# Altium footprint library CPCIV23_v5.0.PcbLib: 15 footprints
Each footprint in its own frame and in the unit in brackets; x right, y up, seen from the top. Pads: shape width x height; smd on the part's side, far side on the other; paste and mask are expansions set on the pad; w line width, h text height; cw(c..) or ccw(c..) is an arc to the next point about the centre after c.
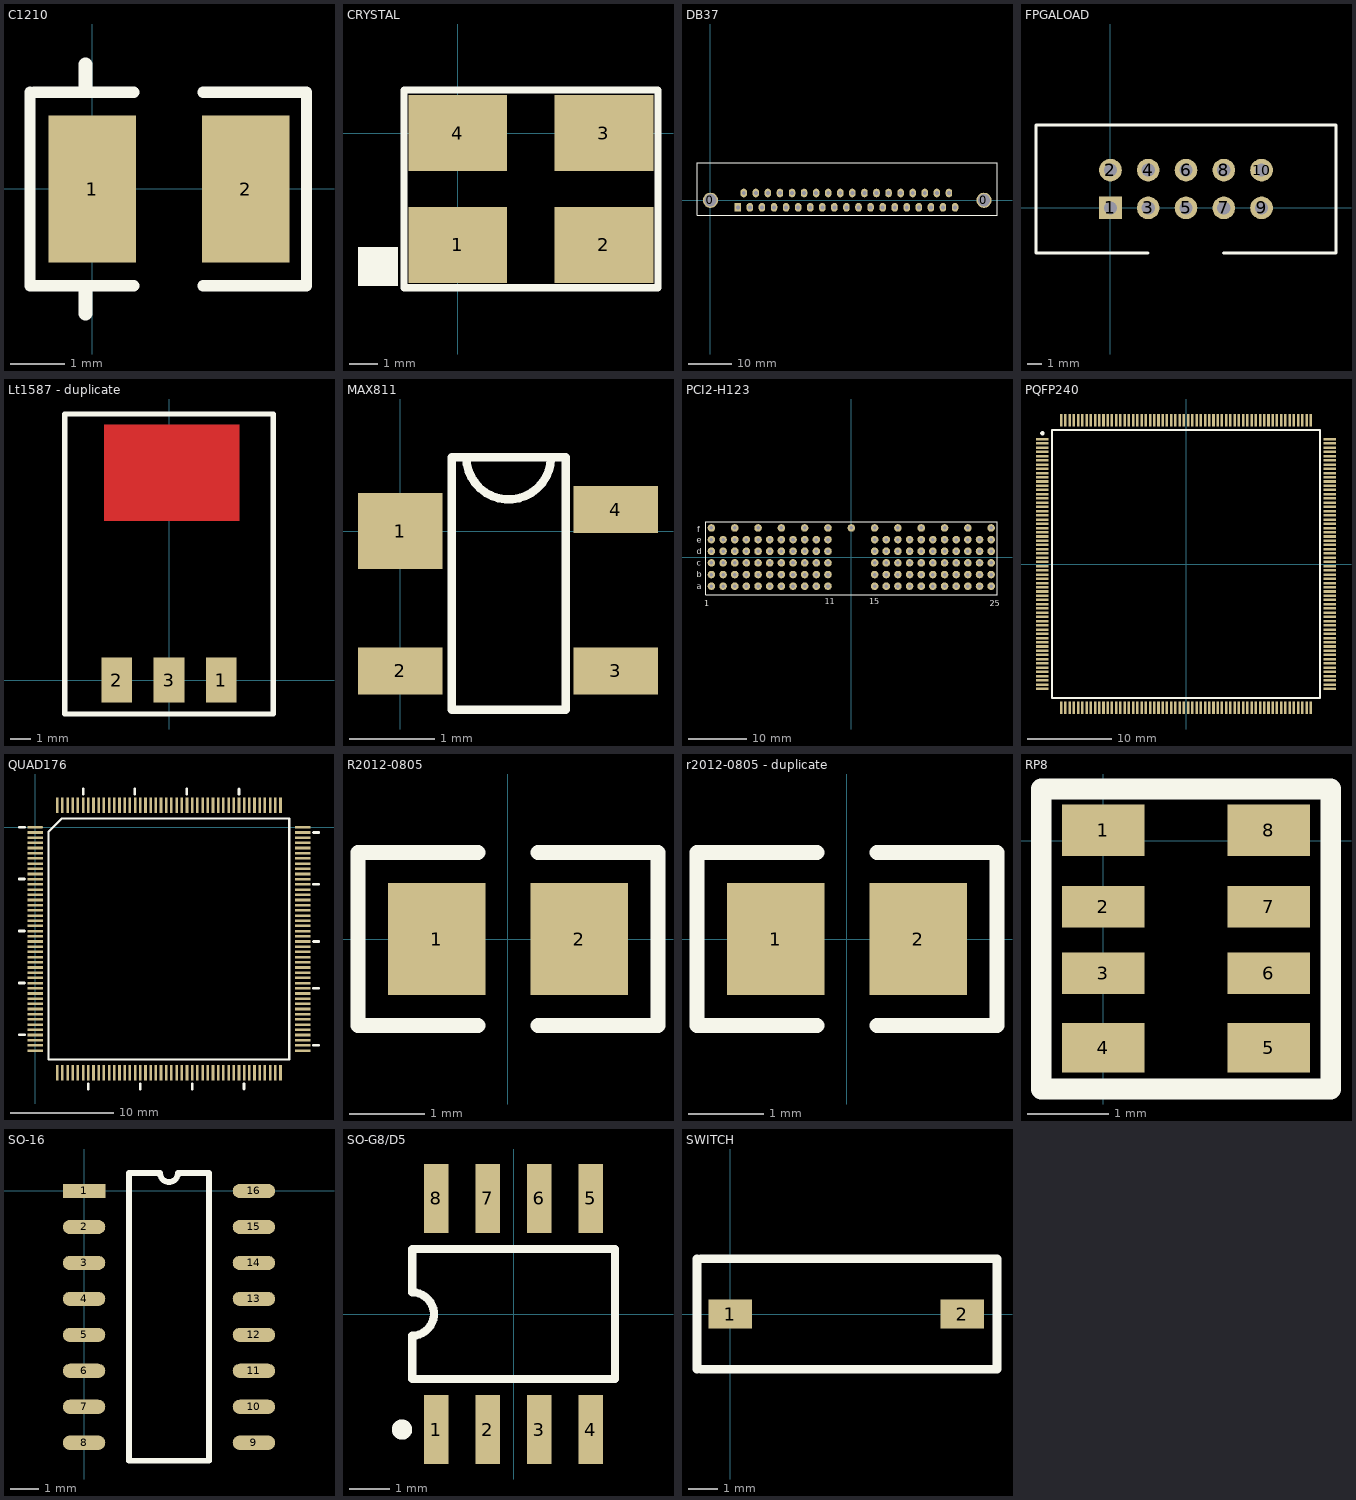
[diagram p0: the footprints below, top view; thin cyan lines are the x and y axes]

## C1210 [mil]
pads (2):
  rect 63x106 smd: 1(0,0) 2(111,0)
Top Overlay:
  lines w8: -45,70 -45,-70 30,-70 ; -42,70 30,70 ; 80,-70 155,-70 155,70 80,70
  lines w10: -5,-90 -5,-75 ; -5,75 -5,90

## CRYSTAL [mm]
height 1.75
pads (4):
  rect 3.5x2.7 smd: 1(0,-3.962) 2(5.182,-3.962) 3(5.182,0) 4(0,0)
Top Overlay:
  rectangle: -3.531,-5.41 -2.108,-4.039
  lines w0.254: -1.905,-4.476 -1.905,1.524 ; 7.095,-4.476 7.095,1.524 ; -1.905,1.524 7.095,1.524 ; -1.905,1.524 -1.905,-5.476 7.095,-5.476 7.095,1.524

## DB37 [mm]
height 1.75
pads (39):
  round 3.5 hole 2.8: 0(0,0) 0(63,0)
  rect 1.5x2 hole 0.9: 1(6.3,-1.62)
  oval 1.5x2 hole 0.9: 2(9.08,-1.62) 3(11.86,-1.62) 4(14.64,-1.62) 5(17.42,-1.62) 6(20.2,-1.62) 7(22.98,-1.62) 8(25.76,-1.62) 9(28.54,-1.62) 10(31.32,-1.62) 11(34.1,-1.62) 12(36.88,-1.62) 13(39.66,-1.62) 14(42.44,-1.62) 15(45.22,-1.62) 16(48,-1.62) 17(50.78,-1.62) 18(53.56,-1.62) 19(56.34,-1.62) 20(7.665,1.68) 21(10.445,1.68) 22(13.225,1.68) 23(16.005,1.68) 24(18.785,1.68) 25(21.565,1.68) 26(24.345,1.68) 27(27.125,1.68) 28(29.905,1.68) 29(32.685,1.68) 30(35.465,1.68) 31(38.245,1.68) 32(41.025,1.68) 33(43.805,1.68) 34(46.585,1.68) 35(49.365,1.68) 36(52.145,1.68) 37(54.925,1.68)
Top Overlay:
  lines w0.254: -3.1,-3.4 -3.1,8.6 66,8.6 66,-3.4 -3.1,-3.4

## FPGALOAD [mil]
pads (10):
  rect 60x60 hole 35: 1(0,0)
  round 60 hole 35: 2(0,100) 3(100,0) 4(100,100) 5(200,0) 6(200,100) 7(300,0) 8(300,100) 9(400,0) 10(400,100)
Top Overlay:
  lines w8: 99,-119 -197,-119 -197,219 597,219 597,-119 299,-119

## Lt1587 - duplicate [mm]
pads (3):
  rect 1.5x2.2 smd: 1(2.54,0) 2(-2.54,0) 3(0,0)
Top Layer:
  rectangle: -3.175,7.747 3.429,12.446
Top Overlay:
  lines w0.254: -5.08,-1.651 5.08,-1.651 5.08,12.954 -5.08,12.954 -5.08,-1.651

## MAX811 [mm]
height 1.75
pads (4):
  rect 1x0.9 smd: 1(0,0)
  rect 1x0.55 smd: 2(0,-1.651) 3(2.54,-1.651) 4(2.54,0.254)
Top Overlay:
  lines w0.1: 0.778,0.873 ccw(c1.278,0.873) 1.778,0.873 ; 1.333,0.873 0.606,0.873 ; 0.606,0.873 1.949,0.873 1.949,-2.111 0.606,-2.111 0.606,0.873

## PCI2-H123 [mm]
pads (123):
  round 1.3 hole 0.61: A1(-24,-5) A2(-22,-5) A3(-20,-5) A4(-18,-5) A5(-16,-5) A6(-14,-5) A7(-12,-5) A8(-10,-5) A9(-8,-5) A10(-6,-5) A11(-4,-5) A15(4,-5) A16(6,-5) A17(8,-5) A18(10,-5) A19(12,-5) A20(14,-5) A21(16,-5) A22(18,-5) A23(20,-5) A24(22,-5) A25(24,-5) B1(-24,-3) B2(-22,-3) B3(-20,-3) B4(-18,-3) B5(-16,-3) B6(-14,-3) B7(-12,-3) B8(-10,-3) B9(-8,-3) B10(-6,-3) B11(-4,-3) B15(4,-3) B16(6,-3) B17(8,-3) B18(10,-3) B19(12,-3) B20(14,-3) B21(16,-3) B22(18,-3) B23(20,-3) B24(22,-3) B25(24,-3) C1(-24,-1) C2(-22,-1) C3(-20,-1) C4(-18,-1) C5(-16,-1) C6(-14,-1) C7(-12,-1) C8(-10,-1) C9(-8,-1) C10(-6,-1) C11(-4,-1) C15(4,-1) C16(6,-1) C17(8,-1) C18(10,-1) C19(12,-1) C20(14,-1) C21(16,-1) C22(18,-1) C23(20,-1) C24(22,-1) C25(24,-1) D1(-24,1) D2(-22,1) D3(-20,1) D4(-18,1) D5(-16,1) D6(-14,1) D7(-12,1) D8(-10,1) D9(-8,1) D10(-6,1) D11(-4,1) D15(4,1) D16(6,1) D17(8,1) D18(10,1) D19(12,1) D20(14,1) D21(16,1) D22(18,1) D23(20,1) D24(22,1) D25(24,1) E1(-24,3) E2(-22,3) E3(-20,3) E4(-18,3) E5(-16,3) E6(-14,3) E7(-12,3) E8(-10,3) E9(-8,3) E10(-6,3) E11(-4,3) E15(4,3) E16(6,3) E17(8,3) E18(10,3) E19(12,3) E20(14,3) E21(16,3) E22(18,3) E23(20,3) E24(22,3) E25(24,3) F1(-24,5) F3(-20,5) F5(-16,5) F7(-12,5) F9(-8,5) F11(-4,5) F13(0,5) F15(4,5) F17(8,5) F19(12,5) F21(16,5) F23(20,5) F25(24,5)
Top Overlay:
  lines w0.2: -25,-6.5 -25,6.1 25,6.1 25,-6.5 -25,-6.5
  text "11" at -4.572,-8.128 h1.02
  text "25" at 23.75,-8.475 h1.02
  text "f" at -26.475,4.225 h1.02
  text "a" at -26.475,-5.5 h1.02
  text "b" at -26.475,-3.5 h1.02
  text "c" at -26.475,-1.5 h1.02
  text "d" at -26.475,0.5 h1.02
  text "e" at -26.475,2.5 h1.02
  text "15" at 3.048,-8.128 h1.02
  text "1" at -25.25,-8.475 h1.02

## PQFP240 [mm]
pads (240):
  rect 1.5x0.3 smd: 1(-16.983,14.75) 2(-16.983,14.25) 3(-16.983,13.75) 4(-16.983,13.25) 5(-16.983,12.75) 6(-16.983,12.25) 7(-16.983,11.75) 8(-16.983,11.25) 9(-16.983,10.75) 10(-16.983,10.25) 11(-16.983,9.75) 12(-16.983,9.25) 13(-16.983,8.75) 14(-16.983,8.25) 15(-16.983,7.75) 16(-16.983,7.25) 17(-16.983,6.75) 18(-16.983,6.25) 19(-16.983,5.75) 20(-16.983,5.25) 21(-16.983,4.75) 22(-16.983,4.25) 23(-16.983,3.75) 24(-16.983,3.25) 25(-16.983,2.75) 26(-16.983,2.25) 27(-16.983,1.75) 28(-16.983,1.25) 29(-16.983,0.75) 30(-16.983,0.25) 31(-16.983,-0.25) 32(-16.983,-0.75) 33(-16.983,-1.25) 34(-16.983,-1.75) 35(-16.983,-2.25) 36(-16.983,-2.75) 37(-16.983,-3.25) 38(-16.983,-3.75) 39(-16.983,-4.25) 40(-16.983,-4.75) 41(-16.983,-5.25) 42(-16.983,-5.75) 43(-16.983,-6.25) 44(-16.983,-6.75) 45(-16.983,-7.25) 46(-16.983,-7.75) 47(-16.983,-8.25) 48(-16.983,-8.75) 49(-16.983,-9.25) 50(-16.983,-9.75) 51(-16.983,-10.25) 52(-16.983,-10.75) 53(-16.983,-11.25) 54(-16.983,-11.75) 55(-16.983,-12.25) 56(-16.983,-12.75) 57(-16.983,-13.25) 58(-16.983,-13.75) 59(-16.983,-14.25) 60(-16.983,-14.75) 121(16.967,-14.75) 122(16.967,-14.25) 123(16.967,-13.75) 124(16.967,-13.25) 125(16.967,-12.75) 126(16.967,-12.25) 127(16.967,-11.75) 128(16.967,-11.25) 129(16.967,-10.75) 130(16.967,-10.25) 131(16.967,-9.75) 132(16.967,-9.25) 133(16.967,-8.75) 134(16.967,-8.25) 135(16.967,-7.75) 136(16.967,-7.25) 137(16.967,-6.75) 138(16.967,-6.25) 139(16.967,-5.75) 140(16.967,-5.25) 141(16.967,-4.75) 142(16.967,-4.25) 143(16.967,-3.75) 144(16.967,-3.25) 145(16.967,-2.75) 146(16.967,-2.25) 147(16.967,-1.75) 148(16.967,-1.25) 149(16.967,-0.75) 150(16.967,-0.25) 151(16.967,0.25) 152(16.967,0.75) 153(16.967,1.25) 154(16.967,1.75) 155(16.967,2.25) 156(16.967,2.75) 157(16.967,3.25) 158(16.967,3.75) 159(16.967,4.25) 160(16.967,4.75) 161(16.967,5.25) 162(16.967,5.75) 163(16.967,6.25) 164(16.967,6.75) 165(16.967,7.25) 166(16.967,7.75) 167(16.967,8.25) 168(16.967,8.75) 169(16.967,9.25) 170(16.967,9.75) 171(16.967,10.25) 172(16.967,10.75) 173(16.967,11.25) 174(16.967,11.75) 175(16.967,12.25) 176(16.967,12.75) 177(16.967,13.25) 178(16.967,13.75) 179(16.967,14.25) 180(16.967,14.75)
  rect 0.3x1.5 smd: 61(-14.758,-16.975) 62(-14.258,-16.975) 63(-13.758,-16.975) 64(-13.258,-16.975) 65(-12.758,-16.975) 66(-12.258,-16.975) 67(-11.758,-16.975) 68(-11.258,-16.975) 69(-10.758,-16.975) 70(-10.258,-16.975) 71(-9.758,-16.975) 72(-9.258,-16.975) 73(-8.758,-16.975) 74(-8.258,-16.975) 75(-7.758,-16.975) 76(-7.258,-16.975) 77(-6.758,-16.975) 78(-6.258,-16.975) 79(-5.758,-16.975) 80(-5.258,-16.975) 81(-4.758,-16.975) 82(-4.258,-16.975) 83(-3.758,-16.975) 84(-3.258,-16.975) 85(-2.758,-16.975) 86(-2.258,-16.975) 87(-1.758,-16.975) 88(-1.258,-16.975) 89(-0.758,-16.975) 90(-0.258,-16.975) 91(0.242,-16.975) 92(0.742,-16.975) 93(1.242,-16.975) 94(1.742,-16.975) 95(2.242,-16.975) 96(2.742,-16.975) 97(3.242,-16.975) 98(3.742,-16.975) 99(4.242,-16.975) 100(4.742,-16.975) 101(5.242,-16.975) 102(5.742,-16.975) 103(6.242,-16.975) 104(6.742,-16.975) 105(7.242,-16.975) 106(7.742,-16.975) 107(8.242,-16.975) 108(8.742,-16.975) 109(9.242,-16.975) 110(9.742,-16.975) 111(10.242,-16.975) 112(10.742,-16.975) 113(11.242,-16.975) 114(11.742,-16.975) 115(12.242,-16.975) 116(12.742,-16.975) 117(13.242,-16.975) 118(13.742,-16.975) 119(14.242,-16.975) 120(14.742,-16.975) 181(14.742,16.975) 182(14.242,16.975) 183(13.742,16.975) 184(13.242,16.975) 185(12.742,16.975) 186(12.242,16.975) 187(11.742,16.975) 188(11.242,16.975) 189(10.742,16.975) 190(10.242,16.975) 191(9.742,16.975) 192(9.242,16.975) 193(8.742,16.975) 194(8.242,16.975) 195(7.742,16.975) 196(7.242,16.975) 197(6.742,16.975) 198(6.242,16.975) 199(5.742,16.975) 200(5.242,16.975) 201(4.742,16.975) 202(4.242,16.975) 203(3.742,16.975) 204(3.242,16.975) 205(2.742,16.975) 206(2.242,16.975) 207(1.742,16.975) 208(1.242,16.975) 209(0.742,16.975) 210(0.242,16.975) 211(-0.258,16.975) 212(-0.758,16.975) 213(-1.258,16.975) 214(-1.758,16.975) 215(-2.258,16.975) 216(-2.758,16.975) 217(-3.258,16.975) 218(-3.758,16.975) 219(-4.258,16.975) 220(-4.758,16.975) 221(-5.258,16.975) 222(-5.758,16.975) 223(-6.258,16.975) 224(-6.758,16.975) 225(-7.258,16.975) 226(-7.758,16.975) 227(-8.258,16.975) 228(-8.758,16.975) 229(-9.258,16.975) 230(-9.758,16.975) 231(-10.258,16.975) 232(-10.758,16.975) 233(-11.258,16.975) 234(-11.758,16.975) 235(-12.258,16.975) 236(-12.758,16.975) 237(-13.258,16.975) 238(-13.758,16.975) 239(-14.258,16.975) 240(-14.758,16.975)
Top Overlay:
  circle w0.25: c-16.983,15.45 r0.125
  lines w0.2: -15.833,-15.825 15.817,-15.825 15.817,15.825 -15.833,15.825 -15.833,-15.825

## QUAD176 [mm]
pads (176):
  oval 1.5x0.25 smd: 1(0,0)
  rect 1.5x0.25 smd: 2(0,-0.5) 3(0,-1) 4(0,-1.5) 5(0,-2) 6(0,-2.5) 7(0,-3) 8(0,-3.5) 9(0,-4) 10(0,-4.5) 11(0,-5) 12(0,-5.5) 13(0,-6) 14(0,-6.5) 15(0,-7) 16(0,-7.5) 17(0,-8) 18(0,-8.5) 19(0,-9) 20(0,-9.5) 21(0,-10) 22(0,-10.5) 23(0,-11) 24(0,-11.5) 25(0,-12) 26(0,-12.5) 27(0,-13) 28(0,-13.5) 29(0,-14) 30(0,-14.5) 31(0,-15) 32(0,-15.5) 33(0,-16) 34(0,-16.5) 35(0,-17) 36(0,-17.5) 37(0,-18) 38(0,-18.5) 39(0,-19) 40(0,-19.5) 41(0,-20) 42(0,-20.5) 43(0,-21) 44(0,-21.5) 89(25.75,-21.5) 90(25.75,-21) 91(25.75,-20.5) 92(25.75,-20) 93(25.75,-19.5) 94(25.75,-19) 95(25.75,-18.5) 96(25.75,-18) 97(25.75,-17.5) 98(25.75,-17) 99(25.75,-16.5) 100(25.75,-16) 101(25.75,-15.5) 102(25.75,-15) 103(25.75,-14.5) 104(25.75,-14) 105(25.75,-13.5) 106(25.75,-13) 107(25.75,-12.5) 108(25.75,-12) 109(25.75,-11.5) 110(25.75,-11) 111(25.75,-10.5) 112(25.75,-10) 113(25.75,-9.5) 114(25.75,-9) 115(25.75,-8.5) 116(25.75,-8) 117(25.75,-7.5) 118(25.75,-7) 119(25.75,-6.5) 120(25.75,-6) 121(25.75,-5.5) 122(25.75,-5) 123(25.75,-4.5) 124(25.75,-4) 125(25.75,-3.5) 126(25.75,-3) 127(25.75,-2.5) 128(25.75,-2) 129(25.75,-1.5) 130(25.75,-1) 131(25.75,-0.5) 132(25.75,0)
  rect 0.25x1.5 smd: 45(2.125,-23.625) 46(2.625,-23.625) 47(3.125,-23.625) 48(3.625,-23.625) 49(4.125,-23.625) 50(4.625,-23.625) 51(5.125,-23.625) 52(5.625,-23.625) 53(6.125,-23.625) 54(6.625,-23.625) 55(7.125,-23.625) 56(7.625,-23.625) 57(8.125,-23.625) 58(8.625,-23.625) 59(9.125,-23.625) 60(9.625,-23.625) 61(10.125,-23.625) 62(10.625,-23.625) 63(11.125,-23.625) 64(11.625,-23.625) 65(12.125,-23.625) 66(12.625,-23.625) 67(13.125,-23.625) 68(13.625,-23.625) 69(14.125,-23.625) 70(14.625,-23.625) 71(15.125,-23.625) 72(15.625,-23.625) 73(16.125,-23.625) 74(16.625,-23.625) 75(17.125,-23.625) 76(17.625,-23.625) 77(18.125,-23.625) 78(18.625,-23.625) 79(19.125,-23.625) 80(19.625,-23.625) 81(20.125,-23.625) 82(20.625,-23.625) 83(21.125,-23.625) 84(21.625,-23.625) 85(22.125,-23.625) 86(22.625,-23.625) 87(23.125,-23.625) 88(23.625,-23.625) 133(23.625,2.125) 134(23.125,2.125) 135(22.625,2.125) 136(22.125,2.125) 137(21.625,2.125) 138(21.125,2.125) 139(20.625,2.125) 140(20.125,2.125) 141(19.625,2.125) 142(19.125,2.125) 143(18.625,2.125) 144(18.125,2.125) 145(17.625,2.125) 146(17.125,2.125) 147(16.625,2.125) 148(16.125,2.125) 149(15.625,2.125) 150(15.125,2.125) 151(14.625,2.125) 152(14.125,2.125) 153(13.625,2.125) 154(13.125,2.125) 155(12.625,2.125) 156(12.125,2.125) 157(11.625,2.125) 158(11.125,2.125) 159(10.625,2.125) 160(10.125,2.125) 161(9.625,2.125) 162(9.125,2.125) 163(8.625,2.125) 164(8.125,2.125) 165(7.625,2.125) 166(7.125,2.125) 167(6.625,2.125) 168(6.125,2.125) 169(5.625,2.125) 170(5.125,2.125) 171(4.625,2.125) 172(4.125,2.125) 173(3.625,2.125) 174(3.125,2.125) 175(2.625,2.125) 176(2.125,2.125)
Top Overlay:
  lines w0.2: 1.285,-22.34 1.285,-0.445 2.57,0.84 24.465,0.84 24.465,-22.34 1.285,-22.34
  lines w0.254: -1.524,-19.99 -1.016,-19.99 ; -1.524,-14.986 -1.016,-14.986 ; -1.524,-9.982 -1.016,-9.982 ; -1.524,-4.978 -1.016,-4.978 ; -1.524,0 -1.016,0 ; 4.623,3.175 4.623,3.683 ; 5.105,-25.197 5.105,-24.689 ; 9.601,3.175 9.601,3.683 ; 10.109,-25.197 10.109,-24.689 ; 14.605,3.175 14.605,3.683 ; 15.113,-25.197 15.113,-24.689 ; 19.634,3.175 19.634,3.683 ; 20.117,-25.197 20.117,-24.689 ; 26.797,-20.98 27.305,-20.98 ; 26.797,-15.494 27.305,-15.494 ; 26.797,-10.998 27.305,-10.998 ; 26.797,-5.486 27.305,-5.486 ; 26.797,-0.508 27.305,-0.508

## R2012-0805 [mm]
height 1.75
pads (2):
  rect 1.3x1.5 smd: 1(-0.95,0) 2(0.95,0)
Top Overlay:
  lines w0.2: -0.4,-1.15 -2,-1.15 -2,1.15 -0.4,1.15 ; 0.4,-1.15 2,-1.15 2,1.15 0.4,1.15

## r2012-0805 - duplicate [mm]
pads (2):
  rect 1.3x1.5 smd: 1(-0.95,0) 2(0.95,0)
Top Overlay:
  lines w0.2: -0.4,-1.15 -2,-1.15 -2,1.15 -0.4,1.15 ; 0.4,-1.15 2,-1.15 2,1.15 0.4,1.15

## RP8 [mil]
pads (8):
  rect 40x25 smd: 1(0,5) 8(80,5)
  rect 40x20 smd: 2(0,-32) 3(0,-64) 6(80,-64) 7(80,-32)
  rect 40x24 smd: 4(0,-100) 5(80,-100)
Top Overlay:
  lines w10: -30,-120 110,-120 110,25 -30,25 -30,-120

## SO-16 [mm]
height 1.75
pads (16):
  rect 1.5x0.5 smd: 1(0,0)
  oval 1.5x0.5 smd: 2(0,-1.27) 3(0,-2.54) 4(0,-3.81) 5(0,-5.08) 6(0,-6.35) 7(0,-7.62) 8(0,-8.89) 9(6,-8.89) 10(6,-7.62) 11(6,-6.35) 12(6,-5.08) 13(6,-3.81) 14(6,-2.54) 15(6,-1.27) 16(6,0)
Top Overlay:
  lines w0.2: 1.585,-9.525 4.415,-9.525 4.415,0.635 3.317,0.635 cw(c3,0.635) 2.682,0.635 1.585,0.635 1.585,-9.525

## SO-G8/D5 [mm]
height 1.75
pads (8):
  rect 0.6x1.7 smd: 1(-1.905,-2.85) 2(-0.635,-2.85) 3(0.635,-2.85) 4(1.905,-2.85) 5(1.905,2.85) 6(0.635,2.85) 7(-0.635,2.85) 8(-1.905,2.85)
Top Overlay:
  circle w0.25: c-2.755,-2.85 r0.125
  lines w0.2: -2.5,-0.533 -2.5,-1.6 2.5,-1.6 2.5,1.6 -2.5,1.6 -2.5,0.533 ; -2.5,-0.533 ccw(c-2.5,0) -2.5,0.533

## SWITCH [mm]
height 1.75
pads (2):
  rect 1.5x1 smd: 1(0,0) 2(8.001,0)
Top Overlay:
  lines w0.305: -1.143,-1.905 -1.143,1.905 ; -1.016,-1.905 9.191,-1.905 9.191,1.905 -1.016,1.905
